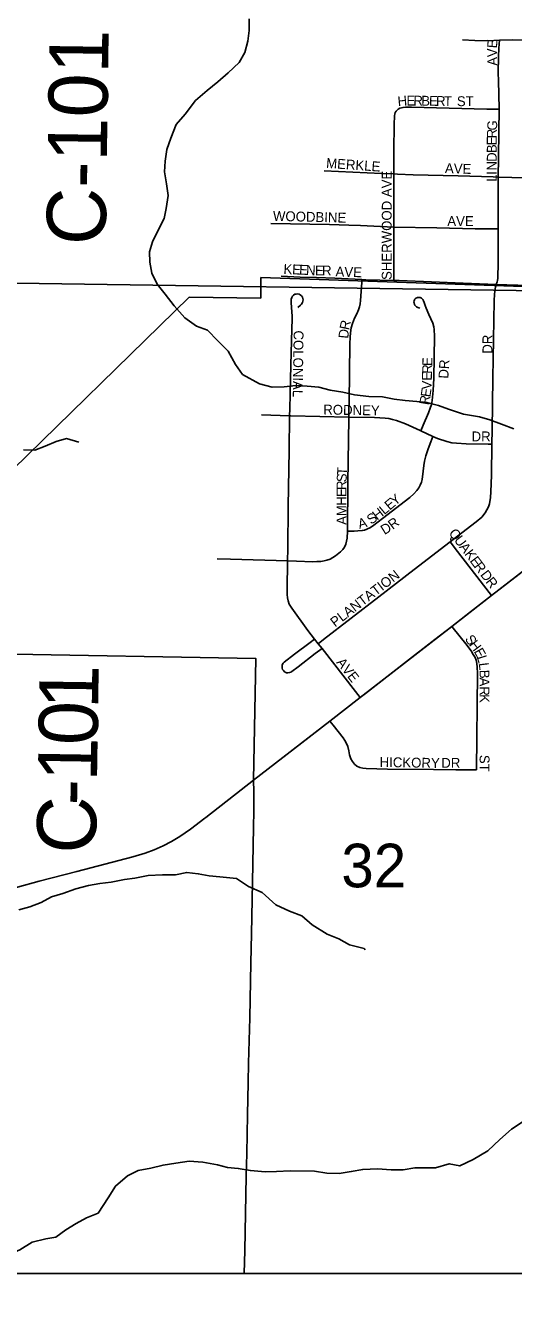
# Model space of a CAD drawing. Extents: x -9.1 to 34, y -3.1 to 22.
# Drawn here: x 3.493 to 3.961, y 17.795 to 19.029 of the extents above; entities that cross this region are included whole.
import ezdxf

# ---------------------------------------------------------------- set-up
doc = ezdxf.new("R2010")
doc.units = 0
for name, color, linetype in [('GM_X_City_Street', 7, 'Continuous'), ('GM_X_City_Street_Text', 7, 'Continuous'), ('GM_X_Corporation', 7, 'Continuous'), ('GM_X_County_Road', 7, 'Continuous'), ('GM_X_County_Road_Text', 7, 'Continuous'), ('GM_X_Minor_River', 7, 'Continuous'), ('GM_X_Section', 7, 'Continuous'), ('GM_X_Section_Text', 7, 'Continuous'), ('GM_X_State_Route', 7, 'Continuous'), ('GM_X_Township_Subdivision', 7, 'Continuous'), ('GM_X_Township_Subdivision_Text', 7, 'Continuous'), ('SH_Text', 7, 'Continuous')]:
    doc.layers.add(name, color=color, linetype=linetype)

msp = doc.modelspace()

# ---------------------------------------------------------------- linework, layer by layer
at = {"layer": 'GM_X_City_Street'}
for points in [[(3.8029, 18.6535), (3.8034, 18.6743), (3.8035, 18.6898), (3.8038, 18.7053), (3.8039, 18.7145), (3.8041, 18.7238), (3.8043, 18.7301), (3.8047, 18.7343), (3.8054, 18.7393), (3.8065, 18.7433), (3.8086, 18.7485), (3.8106, 18.7527), (3.8124, 18.7564), (3.8134, 18.7594), (3.8139, 18.7621), (3.8143, 18.7655), (3.8154, 18.7825), (3.8156, 18.7855)], [(3.9403, 18.6274), (3.9405, 18.6412), (3.9413, 18.6907), (3.9426, 18.765), (3.9428, 18.7713), (3.9433, 18.7765), (3.9443, 18.7807)], [(3.7462, 18.6548), (3.7463, 18.6614), (3.7467, 18.6755), (3.7474, 18.7032), (3.7482, 18.7382), (3.7486, 18.7474), (3.7486, 18.7507), (3.7484, 18.7543), (3.7477, 18.7634), (3.7477, 18.7649), (3.7478, 18.7666), (3.7482, 18.7681), (3.7489, 18.7694), (3.7499, 18.7705), (3.7513, 18.7713), (3.7525, 18.7716), (3.7539, 18.7717), (3.7553, 18.7713), (3.7562, 18.7708), (3.7575, 18.7697), (3.7584, 18.7685), (3.7589, 18.7672), (3.7592, 18.7659), (3.759, 18.7646), (3.7585, 18.7635), (3.7575, 18.762), (3.7566, 18.7609), (3.7542, 18.7588)], [(3.872, 18.6403), (3.8744, 18.6457), (3.8795, 18.6576), (3.8811, 18.662), (3.8823, 18.6657), (3.883, 18.6693), (3.8834, 18.6725), (3.8839, 18.6791), (3.8845, 18.6908), (3.8853, 18.7313), (3.885, 18.7375), (3.8846, 18.7401), (3.8837, 18.7436), (3.8799, 18.7521), (3.8772, 18.7581), (3.8762, 18.7607), (3.8752, 18.7636), (3.8747, 18.7651), (3.8739, 18.7664), (3.8734, 18.767), (3.8728, 18.7676), (3.8722, 18.768), (3.8715, 18.7682), (3.8707, 18.7683), (3.8698, 18.7684), (3.8689, 18.7683), (3.8682, 18.768), (3.8673, 18.7675), (3.8664, 18.7666), (3.866, 18.7659), (3.8656, 18.7649), (3.8655, 18.7638), (3.8656, 18.763), (3.866, 18.7616), (3.8664, 18.7609), (3.8669, 18.7602), (3.8681, 18.7593), (3.8692, 18.7588), (3.8703, 18.7584), (3.8713, 18.7581)], [(3.7193, 18.6558), (3.7462, 18.6548)], [(3.7442, 18.5155), (3.7444, 18.5272), (3.7449, 18.5679), (3.7457, 18.6213), (3.7462, 18.6548)], [(3.7462, 18.6548), (3.7472, 18.6547), (3.8029, 18.6535)], [(3.8016, 18.5439), (3.8021, 18.5904), (3.8029, 18.6521), (3.8029, 18.6535)], [(3.8029, 18.6535), (3.8275, 18.653), (3.8329, 18.6528), (3.8379, 18.6524), (3.8414, 18.652), (3.8448, 18.6513), (3.8486, 18.6502), (3.8575, 18.6469), (3.8714, 18.6406), (3.872, 18.6403)], [(3.8016, 18.5439), (3.8082, 18.5441), (3.8118, 18.5443), (3.8159, 18.5446), (3.8181, 18.5451), (3.8203, 18.5459), (3.8238, 18.5476), (3.827, 18.5497), (3.8354, 18.5561), (3.8614, 18.5764), (3.8653, 18.5799), (3.8682, 18.583), (3.8701, 18.5855), (3.8716, 18.5881), (3.8727, 18.591), (3.8733, 18.5937), (3.8743, 18.6015), (3.8749, 18.6071), (3.8756, 18.6113), (3.8769, 18.6163), (3.8791, 18.6229), (3.8817, 18.6298), (3.8837, 18.635)], [(3.872, 18.6403), (3.8837, 18.635)], [(3.8837, 18.635), (3.8882, 18.633), (3.8971, 18.63), (3.9017, 18.6289), (3.9063, 18.6283), (3.9157, 18.6278), (3.9368, 18.6275), (3.9403, 18.6274)], [(3.9002, 18.5339), (3.903, 18.536), (3.9251, 18.553), (3.9305, 18.5575), (3.934, 18.5617), (3.9371, 18.5672), (3.938, 18.5701), (3.939, 18.5763), (3.9393, 18.5819), (3.9398, 18.5979), (3.9403, 18.6274)], [(3.7442, 18.5155), (3.7528, 18.5152), (3.7686, 18.5147), (3.7723, 18.5148), (3.7761, 18.5149), (3.7793, 18.5154), (3.782, 18.5161), (3.7851, 18.5172), (3.7903, 18.5202), (3.7951, 18.5241), (3.7971, 18.5263), (3.7989, 18.5288), (3.8002, 18.5315), (3.8009, 18.5343), (3.8014, 18.5372), (3.8016, 18.5439)], [(3.7737, 18.436), (3.7788, 18.44), (3.8318, 18.4811), (3.8656, 18.5073), (3.9002, 18.5339)], [(3.9399, 18.4822), (3.9377, 18.4851), (3.9203, 18.5075), (3.9051, 18.5273), (3.9033, 18.5297), (3.9002, 18.5339)], [(3.6766, 18.5176), (3.6896, 18.5171), (3.7442, 18.5155)], [(3.7702, 18.4405), (3.7638, 18.4488), (3.7482, 18.47), (3.7459, 18.474), (3.7447, 18.4772), (3.7441, 18.48), (3.7439, 18.4833), (3.7437, 18.4869), (3.7437, 18.4911), (3.7438, 18.4953), (3.7438, 18.4983), (3.744, 18.5051), (3.7441, 18.5089), (3.7442, 18.5155)], [(3.7773, 18.4314), (3.7708, 18.4265), (3.7544, 18.4138), (3.7484, 18.4094), (3.7472, 18.4087), (3.7462, 18.4083), (3.7445, 18.4081), (3.7433, 18.4082), (3.7419, 18.4088), (3.741, 18.4094), (3.7403, 18.4102), (3.7395, 18.4114), (3.7391, 18.4126), (3.739, 18.4134), (3.7391, 18.4153), (3.7395, 18.4164), (3.74, 18.4174), (3.741, 18.4184), (3.751, 18.426), (3.7658, 18.4372), (3.7702, 18.4405)], [(3.7737, 18.436), (3.7702, 18.4405)], [(3.7773, 18.4314), (3.7737, 18.436)], [(3.8139, 18.3843), (3.8094, 18.3901), (3.7773, 18.4314)]]:
    msp.add_lwpolyline(points, dxfattribs=at)
at = {"layer": 'GM_X_Corporation'}
msp.add_lwpolyline([(3.9702, 18.7789), (3.7187, 18.7874), (3.7185, 18.7677), (3.6498, 18.7686), (3.466, 18.5895), (3.258, 18.3886), (3.4632, 18.3864), (3.4636, 18.4263), (3.7136, 18.4219), (3.7115, 18.305), (3.7849, 18.3618), (3.8139, 18.3843), (3.9018, 18.4526), (3.9399, 18.4822), (4.0083, 18.5352)], dxfattribs=at)
at = {"layer": 'GM_X_County_Road'}
msp.add_lwpolyline([(3.7027, 17.8317), (3.7031, 17.8536), (3.7045, 17.9249), (3.705, 17.9466), (3.7058, 17.9839), (3.7065, 18.0149), (3.7066, 18.0335), (3.7079, 18.0769), (3.7088, 18.1297), (3.7096, 18.1575), (3.7104, 18.2072), (3.7115, 18.2599), (3.7118, 18.2754), (3.7118, 18.2831), (3.7117, 18.2939), (3.7115, 18.305)], dxfattribs=at)
at = {"layer": 'GM_X_Minor_River'}
for points in [[(3.7075, 19.0356), (3.7073, 19.0246), (3.706, 19.0144), (3.7032, 19.0034), (3.6977, 18.9937), (3.6873, 18.984), (3.6774, 18.9751), (3.667, 18.9669), (3.6559, 18.9572), (3.6459, 18.9441), (3.6374, 18.9344), (3.6323, 18.9213), (3.6283, 18.9103), (3.6266, 18.899), (3.626, 18.8888), (3.6281, 18.8773), (3.6295, 18.8663), (3.6277, 18.8538), (3.6257, 18.844), (3.6194, 18.8316), (3.6147, 18.8218), (3.6116, 18.812), (3.6121, 18.8022), (3.6139, 18.7915), (3.619, 18.7812), (3.6268, 18.7716), (3.6353, 18.7604), (3.6457, 18.7489), (3.6569, 18.7407), (3.6674, 18.7368), (3.6774, 18.7267), (3.6871, 18.7167), (3.6941, 18.7041), (3.7011, 18.6945), (3.7172, 18.6855), (3.7293, 18.6822), (3.741, 18.6824), (3.752, 18.6837), (3.7629, 18.6832), (3.7743, 18.6822), (3.7852, 18.6794), (3.7972, 18.6773), (3.8085, 18.6748), (3.8221, 18.6731), (3.8353, 18.6728), (3.8466, 18.6707), (3.8572, 18.6694), (3.8682, 18.6685), (3.878, 18.6675), (3.8889, 18.6647), (3.8987, 18.6611), (3.913, 18.6563), (3.9284, 18.6538), (3.9382, 18.651), (3.9495, 18.6466), (3.9615, 18.6422)], [(3.4909, 18.6219), (3.5018, 18.6217), (3.5117, 18.6257), (3.522, 18.6301), (3.5322, 18.6329), (3.5439, 18.6293)], [(3.4863, 18.1806), (3.4969, 18.1835), (3.5076, 18.1875), (3.5175, 18.193), (3.5285, 18.1962), (3.541, 18.2009), (3.5532, 18.2041), (3.5642, 18.2058), (3.5748, 18.2072), (3.5877, 18.2096), (3.5975, 18.2109), (3.6104, 18.2134), (3.6241, 18.2143), (3.6365, 18.2141), (3.6475, 18.2165), (3.6585, 18.2152), (3.669, 18.2131), (3.6792, 18.2122)], [(3.6792, 18.2122), (3.6951, 18.2108), (3.7067, 18.203), (3.7198, 18.1971), (3.7328, 18.1855), (3.746, 18.1792), (3.758, 18.1748), (3.7677, 18.1663), (3.7823, 18.1573), (3.7935, 18.1526), (3.8037, 18.1471), (3.8176, 18.1434), (3.8187, 18.1423)], [(3.4992, 17.8615), (3.5121, 17.8647), (3.5219, 17.8664), (3.5315, 17.8735), (3.5414, 17.8794), (3.5514, 17.8849), (3.5624, 17.8896), (3.5721, 17.9043), (3.5791, 17.9155), (3.5906, 17.9252), (3.6009, 17.9303), (3.613, 17.9327), (3.6248, 17.9356), (3.6369, 17.9376), (3.6498, 17.9393), (3.663, 17.9383), (3.677, 17.9358), (3.6867, 17.9334), (3.6969, 17.9324), (3.7086, 17.9303), (3.7226, 17.9293), (3.7336, 17.9295), (3.7468, 17.9301), (3.7699, 17.9297), (3.7819, 17.9279), (3.7936, 17.9277), (3.8054, 17.9294), (3.8164, 17.9315), (3.8304, 17.932), (3.8436, 17.931), (3.8553, 17.9312), (3.8663, 17.9329), (3.8765, 17.9331), (3.8863, 17.933), (3.8993, 17.9369), (3.9094, 17.9348), (3.9224, 17.9411), (3.9365, 17.9492), (3.948, 17.9603), (3.9592, 17.97), (3.9703, 17.9774)], [(3.4176, 17.8317), (3.4231, 17.8333), (3.4337, 17.8365), (3.4447, 17.8378), (3.4546, 17.8414), (3.4653, 17.8447), (3.4755, 17.8491), (3.4873, 17.8542), (3.4992, 17.8615)]]:
    msp.add_lwpolyline(points, dxfattribs=at)
at = {"layer": 'GM_X_Section'}
for points in [[(3.2347, 19.7726), (4.2285, 19.7772), (4.2254, 18.771), (3.222, 18.7858)], [(3.222, 18.7858), (4.2254, 18.771), (4.2125, 17.7717), (3.2094, 17.7781)]]:
    msp.add_lwpolyline(points, close=True, dxfattribs=at)
at = {"layer": 'GM_X_State_Route'}
for points in [[(3.7115, 18.305), (3.7649, 18.3463), (3.7849, 18.3618), (3.8139, 18.3843), (3.8191, 18.3882), (3.8583, 18.419), (3.8855, 18.4399), (3.9018, 18.4526), (3.9199, 18.4667), (3.9399, 18.4822), (3.9569, 18.4953), (4.0036, 18.5316), (4.0083, 18.5352), (4.0298, 18.5517)], [(3.6649, 18.2686), (3.6658, 18.2692), (3.6998, 18.2956), (3.7115, 18.305)], [(3.4639, 18.1965), (3.5059, 18.208), (3.5419, 18.2174), (3.5689, 18.2243), (3.5958, 18.2313), (3.6076, 18.2349), (3.6163, 18.2381), (3.6247, 18.2419), (3.6328, 18.2463), (3.6407, 18.2511), (3.6509, 18.2581), (3.6649, 18.2686)]]:
    msp.add_lwpolyline(points, dxfattribs=at)
at = {"layer": 'GM_X_Township_Subdivision'}
for points in [[(3.9121, 19.0155), (3.9238, 19.015), (3.9366, 19.0147), (3.9475, 19.0153)], [(3.9466, 18.9761), (3.9464, 18.9838), (3.9466, 18.9995), (3.9468, 19.0075), (3.9475, 19.0153)], [(3.9475, 19.0153), (3.9597, 19.0156), (3.9726, 19.0153)], [(3.9473, 18.949), (3.9474, 18.9495), (3.9466, 18.9761)], [(3.8461, 18.8868), (3.8461, 18.9081), (3.8464, 18.9356), (3.8467, 18.9413), (3.8469, 18.9429), (3.8471, 18.9443), (3.8476, 18.9459), (3.8484, 18.9472), (3.8493, 18.9482), (3.8503, 18.949)], [(3.8503, 18.949), (3.8519, 18.9499), (3.8536, 18.9504), (3.8551, 18.9507), (3.8574, 18.9509), (3.8598, 18.9509), (3.8631, 18.9508), (3.9355, 18.9491), (3.9421, 18.949), (3.9473, 18.949)], [(3.9464, 18.8839), (3.9465, 18.9027), (3.947, 18.9277), (3.9473, 18.949)], [(3.7792, 18.8897), (3.8345, 18.8872), (3.8461, 18.8868)], [(3.8462, 18.8358), (3.8462, 18.8397), (3.8461, 18.8735), (3.8461, 18.8868)], [(3.8461, 18.8868), (3.8497, 18.8866), (3.8649, 18.8861), (3.9079, 18.885), (3.9415, 18.8841), (3.9464, 18.8839)], [(3.9462, 18.8341), (3.9462, 18.8423), (3.9464, 18.8542), (3.9464, 18.8688), (3.9464, 18.8839)], [(3.9464, 18.8839), (3.9595, 18.8835), (3.9717, 18.8831)], [(3.7282, 18.8393), (3.7846, 18.8384), (3.8029, 18.8377), (3.8141, 18.8372), (3.8462, 18.8358)], [(3.8462, 18.7846), (3.8462, 18.7904), (3.8462, 18.8358)], [(3.8462, 18.8358), (3.8874, 18.8352), (3.9241, 18.8343), (3.9419, 18.8341), (3.9462, 18.8341)], [(3.9443, 18.7807), (3.9453, 18.7832), (3.9456, 18.7846), (3.9459, 18.7869), (3.9462, 18.8018), (3.9462, 18.8341)], [(3.7382, 18.7886), (3.7562, 18.7878), (3.772, 18.7874), (3.7897, 18.7867), (3.8156, 18.7855)], [(3.8156, 18.7855), (3.8193, 18.7853), (3.8462, 18.7846)], [(3.8462, 18.7846), (3.8514, 18.7845), (3.8823, 18.7833), (3.9128, 18.782), (3.9443, 18.7807)], [(3.9443, 18.7807), (3.9652, 18.78), (3.9709, 18.7797)], [(3.9018, 18.4526), (3.9032, 18.4509), (3.9152, 18.4358), (3.9203, 18.429), (3.9224, 18.4256), (3.9242, 18.4226), (3.9252, 18.4201), (3.926, 18.4171), (3.9263, 18.4135), (3.9265, 18.4077), (3.9256, 18.315)], [(3.7849, 18.3618), (3.7881, 18.3578), (3.7977, 18.3457), (3.7993, 18.3432), (3.8012, 18.3397), (3.802, 18.3375), (3.8029, 18.3332), (3.8036, 18.3295), (3.8048, 18.3256), (3.8064, 18.3228), (3.8083, 18.3204), (3.8107, 18.3186), (3.8135, 18.3173), (3.8165, 18.3164), (3.8196, 18.3161), (3.8401, 18.3157), (3.8841, 18.3152), (3.9057, 18.3151), (3.9256, 18.315)]]:
    msp.add_lwpolyline(points, dxfattribs=at)
at = {"layer": 'SH_Text'}
msp.add_lwpolyline([(2.873, 17.8317), (4.5258, 17.8317), (4.5258, 17.1445), (2.873, 17.1445)], close=True, dxfattribs=at)

# ---------------------------------------------------------------- texts
at = {"layer": 'GM_X_City_Street_Text'}
for s, rotation, p in [('R', 78.0613, (3.8032, 18.7365)), ('COLONIAL', 269.1935, (3.7501, 18.7367)), ('D', 84.3525, (3.8024, 18.7285)), ('DR', 90, (3.9407, 18.7143)), ('E', 88.6341, (3.883, 18.7024)), ('DR', 86.989, (3.8985, 18.6902)), ('E', 88.6327, (3.8826, 18.6883)), ('R', 88.6349, (3.8828, 18.6949)), ('E', 81.8033, (3.8812, 18.6722)), ('V', 87.2604, (3.8822, 18.6797)), ('R', 80.7054, (3.8799, 18.6646)), ('RODNEY', 359.0128, (3.7784, 18.656)), ('DR', 0, (3.9208, 18.6302)), ('S', 87.5128, (3.8008, 18.5908)), ('T', 87.0202, (3.8011, 18.5975)), ('R', 89.32, (3.8007, 18.5834)), ('E', 89.9727, (3.8007, 18.5768)), ('H', 89.9781, (3.8007, 18.5684)), ('E', 40.0344, (3.8422, 18.5636)), ('Y', 40.0323, (3.8474, 18.5679)), ('M', 89.9818, (3.8007, 18.5584)), ('A', 89.9781, (3.8007, 18.5501)), ('A', 15.6212, (3.8132, 18.5461)), ('S', 36.0034, (3.8245, 18.55)), ('H', 37.2661, (3.8301, 18.554)), ('L', 39.5484, (3.837, 18.5593)), ('R', 37.0403, (3.8451, 18.5451)), ('D', 31.6347, (3.8372, 18.5402)), ('Q', 307.1715, (3.8984, 18.542)), ('U', 307.1711, (3.9035, 18.5353)), ('A', 307.1711, (3.9085, 18.5287)), ('K', 307.1715, (3.9136, 18.522)), ('E', 307.1669, (3.9186, 18.5154)), ('PLANTATION', 37.6462, (3.7898, 18.4515)), ('R', 307.1614, (3.9226, 18.5101)), ('D', 307.1869, (3.9287, 18.5021)), ('R', 308.2815, (3.9338, 18.4953)), ('AVE', 308.0509, (3.7906, 18.4179))]:
    msp.add_text(s, height=0.00947, rotation=rotation, dxfattribs=at).set_placement(p)
at = {"layer": 'GM_X_County_Road_Text'}
for s, height, rotation, p in [('C-101', 0.05682, 89.1731, (3.5696, 18.8183)), ('1', 0.0568, 89.1635, (3.5624, 18.3731)), ('0', 0.0568, 89.1046, (3.5619, 18.3383)), ('1', 0.0568, 89.0807, (3.5613, 18.3036)), ('-', 0.0568, 89.0746, (3.5609, 18.2805)), ('C', 0.0568, 89.0718, (3.5602, 18.2342))]:
    msp.add_text(s, height=height, rotation=rotation, dxfattribs=at).set_placement(p)
at = {"layer": 'GM_X_Section_Text'}
msp.add_text('32', height=0.04186, rotation=0, dxfattribs=at).set_placement((3.7958, 18.2022))
at = {"layer": 'GM_X_Township_Subdivision_Text'}
for s, rotation, p in [('E', 85.4609, (3.9451, 19.0072)), ('V', 91.6616, (3.9453, 18.9991)), ('A', 92.7336, (3.9457, 18.9908)), ('H', 5.1647, (3.8502, 18.9518)), ('E', 359.8907, (3.8583, 18.9525)), ('R', 359.0286, (3.8649, 18.9525)), ('B', 359.0286, (3.8724, 18.9524)), ('E', 359.0165, (3.8799, 18.9523)), ('R', 359.0315, (3.8866, 18.9522)), ('T', 359.0165, (3.8941, 18.952)), ('ST', 0, (3.9067, 18.9519)), ('R', 88.9557, (3.9449, 18.9209)), ('G', 85.9097, (3.945, 18.9282)), ('E', 89.9707, (3.9449, 18.9143)), ('B', 89.9757, (3.9449, 18.9068)), ('MERKLE', 355.9842, (3.781, 18.8927)), ('D', 89.9812, (3.9449, 18.8984)), ('SHERWOOD AVE', 90, (3.8441, 18.7851)), ('AVE', 358.0261, (3.8951, 18.8877)), ('N', 89.9563, (3.9449, 18.8901)), ('I', 89.985, (3.9449, 18.8859)), ('L', 89.9727, (3.9449, 18.8793)), ('WOODBINE', 358.4934, (3.7301, 18.8419)), ('AVE', 0, (3.8975, 18.8369)), ('K', 357.0044, (3.7401, 18.791)), ('E', 357.0392, (3.7484, 18.7906)), ('E', 357.0202, (3.7551, 18.7903)), ('N', 357.2491, (3.7618, 18.7899)), ('E', 359.0276, (3.7704, 18.7895)), ('R', 359.9687, (3.7773, 18.7894)), ('AVE', 358.0264, (3.7901, 18.7885)), ('S', 306.624, (3.9139, 18.4403)), ('H', 306.6251, (3.9179, 18.435)), ('E', 299.0095, (3.9227, 18.4286)), ('L', 286.8275, (3.9257, 18.4232)), ('L', 276.8743, (3.9276, 18.4173)), ('B', 270.85, (3.9284, 18.4109)), ('A', 270, (3.9285, 18.4035)), ('R', 269.994, (3.9285, 18.3951)), ('K', 269.9928, (3.9285, 18.3876)), ('HICKORY', 359.0765, (3.8325, 18.3177)), ('DR', 0, (3.8917, 18.3169)), ('ST', 270, (3.9285, 18.3293))]:
    msp.add_text(s, height=0.00947, rotation=rotation, dxfattribs=at).set_placement(p)

doc.saveas('drawing.dxf')
